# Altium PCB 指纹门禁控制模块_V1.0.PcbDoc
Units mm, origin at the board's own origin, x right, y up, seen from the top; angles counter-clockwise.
Board outline 60 x 20 mm, 2 copper layers (Top Layer, Bottom Layer); 45 components, 31 nets, 157 pads, 95 vias.
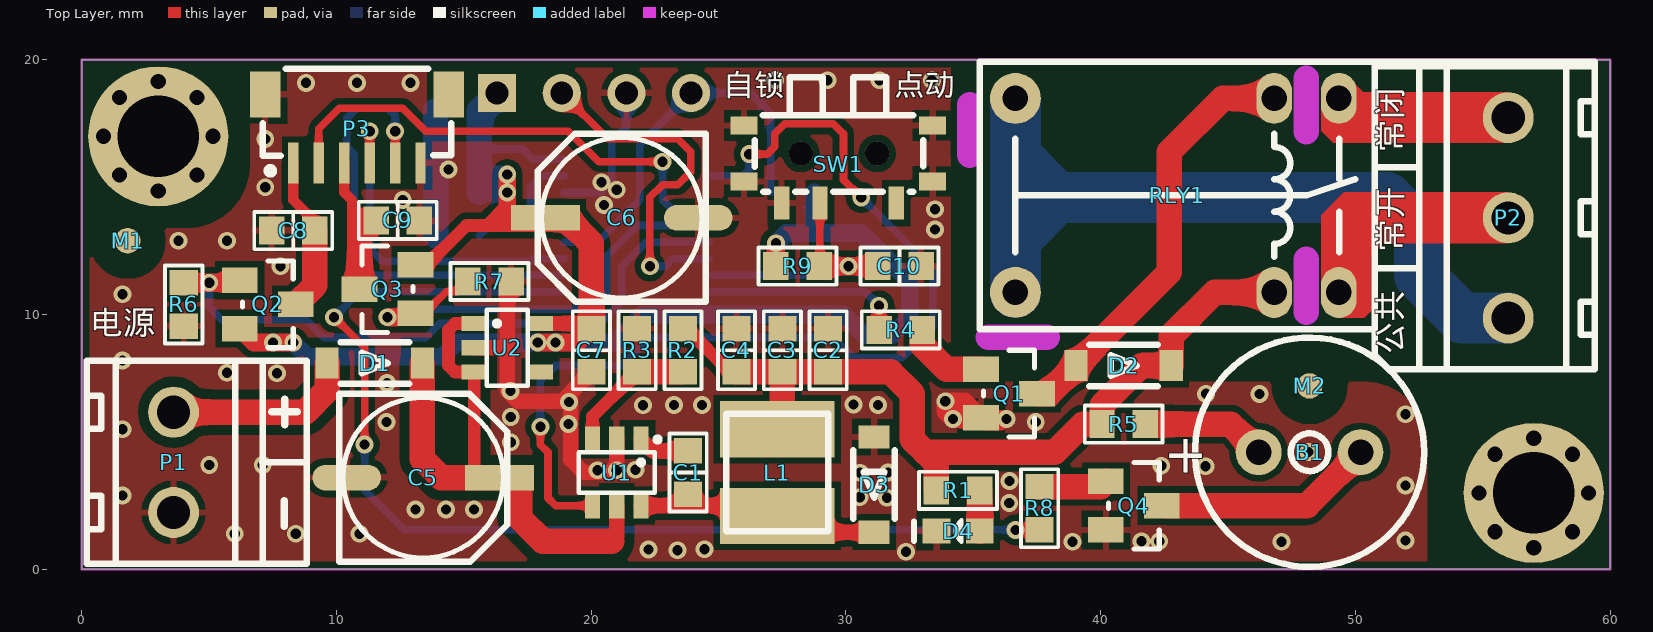
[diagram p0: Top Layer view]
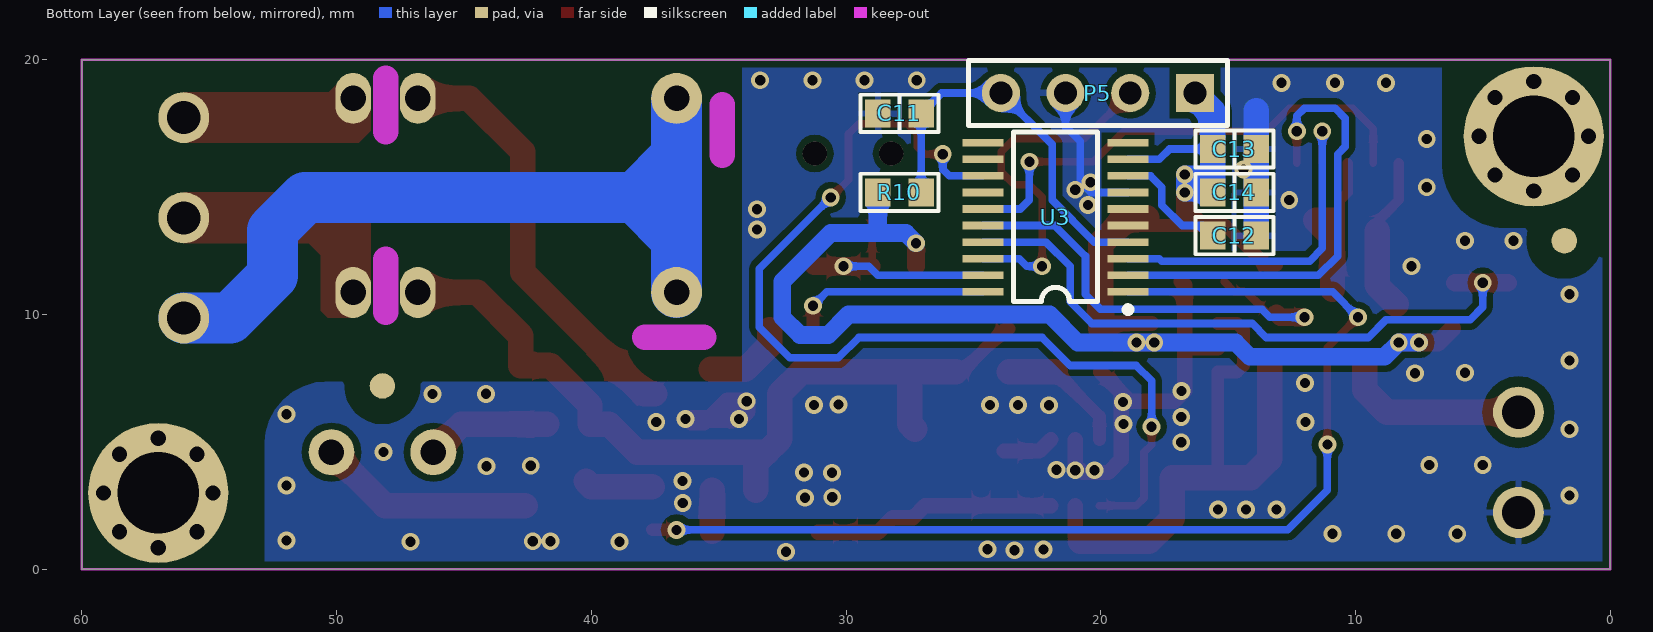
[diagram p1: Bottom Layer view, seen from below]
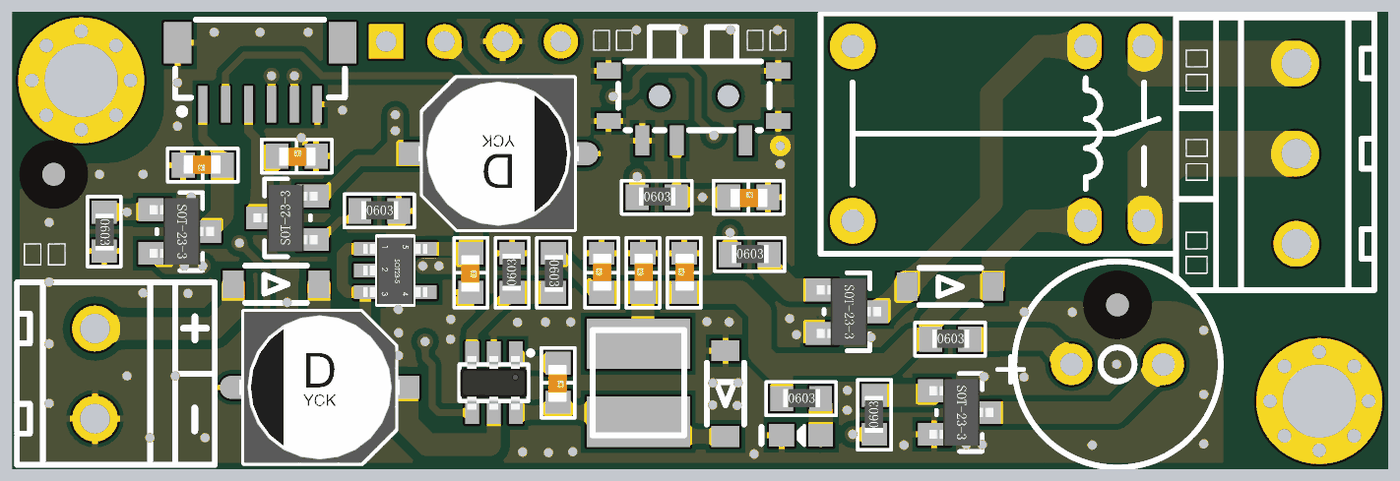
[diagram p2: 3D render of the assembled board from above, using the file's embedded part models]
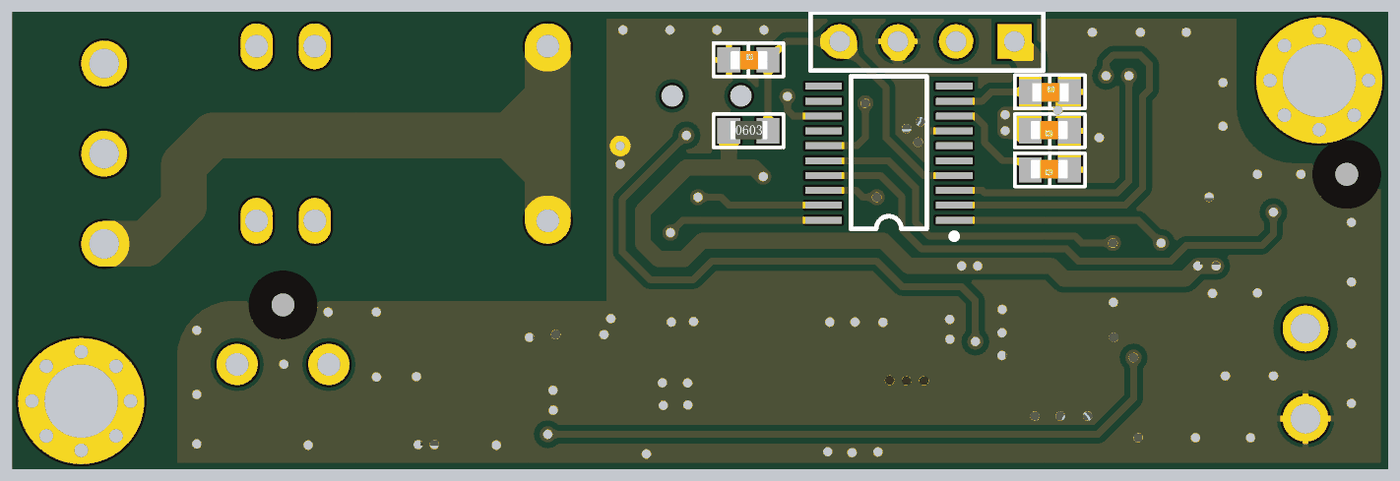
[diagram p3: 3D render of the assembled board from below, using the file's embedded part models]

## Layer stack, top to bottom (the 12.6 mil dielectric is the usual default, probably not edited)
Top Solder: solder mask 0.0102, Solder Resist, Dk 3.5
Top Layer: signal copper 0.0356
Dielectric 1: dielectric 0.32, FR-4, Dk 4.8
Bottom Layer: signal copper 0.0356
Bottom Solder: solder mask 0.0102, Solder Resist, Dk 3.5

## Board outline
0,0 60,0 60,20 0,20

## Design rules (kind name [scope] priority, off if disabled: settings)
Clearance Clearance_1 [InNet('NetD1_1') Or InNet('VIN') vs InPolygon] p1: gap=0.4
Clearance [All] p2: gap=0.254
ComponentClearance [All] p1: gap=0 collisioncheckmode=3 verticalgap=0 showdistances=FALSE
HoleSize [All] p1 off: absolutevalues=TRUE maxlimit=2.54 minlimit=0.025 maxpercent=80.000 minpercent=20.000
HoleToHoleClearance [All] p1 off: gap=0.254 allowstackedmicrovias=TRUE
LayerPairs [All] p1 off: enforce=TRUE
MinimumSolderMaskSliver [All] p1 off: minsoldermaskwidth=0.254
NetAntennae [All] p1 off: netantennaetolerance=0
PolygonConnect PolygonConnect_1 [InNet('GND') And isvia] p1: connectstyle=Direct reliefconductorwidth=0.254 reliefentries=4 polygonreliefangle="90 Angle" airgapwidth=0.254
PolygonConnect [All] p2: connectstyle=Relief reliefconductorwidth=0.254 reliefentries=4 polygonreliefangle="90 Angle" airgapwidth=0.254
RoutingVias [All] p1: holewidth=0.711 width=1.27 viastyle="Through Hole" minholewidth=0.1 minwidth=0.1 maxholewidth=0.711 maxwidth=1.27
SilkToBoardRegionClearance [All] p1 off:
SilkToSilkClearance [All] p1 off: silktosilkclearance=0.254
SilkToSolderMaskClearance [IsPad] p1 off: minsilkscreentomaskgap=0.254 clearancetoexposedcopper=TRUE
SolderMaskExpansion [All] p1: expansion=0.102
Width [All] p1: maxlimit=8 minlimit=0.254 preferedwidth=0.254
21 further rules are at their usual default settings.

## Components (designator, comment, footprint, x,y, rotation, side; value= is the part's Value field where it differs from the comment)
B1 "QMB-09B-03" BUZZER-9MM 48.2,4.6 r0 top
C1 "103 50V 10% X7R 0603" C0603 23.8,3.8 r270 top
C2 "10uF 10V 20% X5R 0603" C0603 29.3,8.6 r90 top
C3 "10uF 10V 20% X5R 0603" C0603 27.5,8.6 r90 top
C4 "104 16V 10% X7R 0603" C0603 25.7,8.6 r90 top
C5 "100uF 35V 贴片电解电容" CAP-D6.3XH7.7 13.4,3.6 r0 top
C6 "220uF 6.3V 贴片电解电容" CAP-D6.3XH7.7 21.2,13.8 r180 top
C7 "104 16V 10% X7R 0603" C0603 20,8.6 r270 top
C8 "104 16V 10% X7R 0603" C0603 8.3,13.3 r180 top
C9 "104 16V 10% X7R 0603" C0603 12.4,13.7 r0 top
C10 "104 16V 10% X7R 0603" C0603 32.1,11.9 r0 top
C11 "104 16V 10% X7R 0603" C0603 27.9,17.9 r180 bottom
C12 "1uF 10V 20% X5R 0603" C0603 14.75,13.1 r0 bottom
C13 "10uF 10V 20% X5R 0603" C0603 14.75,16.5 r180 bottom
C14 "104 16V 10% X7R 0603" C0603 14.75,14.8 r0 bottom
D1 "DSK34" SOD-123 11.5,8.1 r0 top
D2 "DSK34" SOD-123 40.9,8 r0 top
D3 "DSK34" SOD-123 31.1,3.325 r270 top
D4 "黄绿色 贴片LED" LED-0603 34.4,1.5 r180 top
L1 "4.7uH" L-SMD-4.5X4.0 27.3,3.8 r90 top
M1 "MARK" MARK 1.8,12.9 r0 top
M2 "MARK" MARK 48.2,7.2 r0 top
P1 "KF396-2 接线端子" KF396-2 3.6,4.2 r270 top
P2 "KF396-3 接线端子" KF396-3 56,13.8 r90 top
P3 "6P-1.0mm-立式贴片插座" "SH 1.0_LS_6P" 10.8,17.3 r0 top
P5 "STM8 烧写口" HDR1X4 16.3,18.7 r0 bottom
Q1 "S8050" SOT-23 36.4,6.9 r270 top
Q2 "SI2301" SOT-23 7.3,10.4 r270 top
Q3 "SI2301" SOT-23 12,11 r90 top
Q4 "S8050" SOT-23 41.3,2.5 r270 top
R1 "1K 1% 0603" R0603 34.4,3.1 r0 top
R2 "75K 1% 0603" R0603 23.6,8.6 r270 top
R3 "24K 1% 0603" R0603 21.8,8.6 r90 top
R4 "1K 1% 0603" R0603 32.15,9.4 r0 top
R5 "100R 1% 0603" R0603 40.9,5.7 r0 top
R6 "10K 1% 0603" R0603 4,10.4 r270 top
R7 "10K 1% 0603" R0603 16,11.3 r0 top
R8 "1K 1% 0603" R0603 37.6,2.4 r90 top
R9 "10K 1% 0603" R0603 28.1,11.9 r0 top
R10 "10K 1% 0603" R0603 27.9,14.8 r180 bottom
RLY1 "HK4100F-DC3V-SHG" RELAY-TH_HK4100F-XXX-XXXX 43,14.68 r180 top
SW1 "MSK12CO2-BDM" SW-SMD_MSK12CO2-BDM 29.7,15.9 r180 top
U1 "EUP3458VIR1" SOT-23-6 21,3.8 r180 top
U2 "HT7533" SOT-23-5 16.7,8.7 r270 top
U3 "STM8S003F3P6" TSSOP-20 21.7,14 r90 bottom

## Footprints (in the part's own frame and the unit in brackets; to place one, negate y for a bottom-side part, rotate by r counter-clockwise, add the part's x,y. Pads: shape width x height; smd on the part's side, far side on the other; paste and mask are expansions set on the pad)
BUZZER-9MM [mm]
  round 1.8 hole 1: 1(-2,0) 2(2,0)
  silkscreen extent -4.5,-4.5 4.5,4.5
C0603 [mm]
  rect 1x1.1 smd: 1(-0.85,0) 2(0.85,0)
  silkscreen extent -1.53,-0.73 1.53,0.73, body extent -0.78,-0.42 0.82,0.38, height 0.3
CAP-D6.3XH7.7 [mm] "贴片电解电容，直径6.3mm，高7.7mm"
  rect 2.7x1 smd: 1(3,0)
  oval 2.7x1 smd: 2(-3,0)
  silkscreen extent -3.3,-3.3 3.3,3.3, body extent -3.5,-3.3 3.5,3.3, height 7.7
HDR1X4 [mm] "Connector; Header; 4 Position"
  rect 1.5x1.5 hole 0.9: 1(0,0)
  round 1.5 hole 0.9: 2(2.54,0) 3(5.08,0) 4(7.62,0)
  silkscreen extent -1.27,-1.27 8.89,1.27
KF396-2 [mm]
  round 2 hole 1.3: 1(-1.968,0) 2(1.968,0)
  silkscreen extent -3.98,-3.4 3.98,3.5
KF396-3 [mm]
  round 2 hole 1.3: 1(-3.937,0) 2(0,0) 3(3.937,0)
  silkscreen extent -5.95,-3.4 5.95,3.5
L-SMD-4.5X4.0 [mm]
  rect 2.2x4.5 smd: 1(-1.7,0) 2(1.7,0)
  silkscreen extent -2.3,-2 2.3,2
LED-0603 [mil]
  rect 43x39 smd: 1(-33.5,0) 2(33.5,0)
  silkscreen extent -6,-17 68,17
MARK [mm] "MARK点，外径3mm，内径1mm"
  round 1 smd: 1(0,0)
  round 1 smd far side: 1(0,0)
  Top Layer pour cut-out: 0,1.5 0.074,1.5 0.294,1.478 0.577,1.393 0.837,1.253 1.066,1.066 1.253,0.837 1.393,0.577 1.478,0.294 1.5,0.074 1.5,0 1.5,0 1.5,0 1.5,-0.074 1.478,-0.294 1.393,-0.577 1.253,-0.837 1.066,-1.066 0.837,-1.253 0.577,-1.393 0.294,-1.478 0.074,-1.5 0,-1.5 0,-1.5 -0.074,-1.5 -0.294,-1.478 -0.577,-1.393 -0.837,-1.253 -1.066,-1.066 -1.253,-0.837 -1.393,-0.577 -1.478,-0.294 -1.5,-0.074 -1.5,0 -1.5,0 -1.5,0 -1.5,0.074 -1.478,0.294 -1.393,0.577 -1.253,0.837 -1.066,1.066 -0.837,1.253 -0.577,1.393 -0.294,1.478 -0.074,1.5 0,1.5
  Bottom Layer pour cut-out: 0,1.5 -0.074,1.5 -0.294,1.478 -0.577,1.393 -0.837,1.253 -1.066,1.066 -1.253,0.837 -1.393,0.577 -1.478,0.294 -1.5,0.074 -1.5,0 -1.5,0 -1.5,0 -1.5,-0.074 -1.478,-0.294 -1.393,-0.577 -1.253,-0.837 -1.066,-1.066 -0.837,-1.253 -0.577,-1.393 -0.294,-1.478 -0.074,-1.5 0,-1.5 0,-1.5 0.074,-1.5 0.294,-1.478 0.577,-1.393 0.837,-1.253 1.066,-1.066 1.253,-0.837 1.393,-0.577 1.478,-0.294 1.5,-0.074 1.5,0 1.5,0 1.5,0 1.5,0.074 1.478,0.294 1.393,0.577 1.253,0.837 1.066,1.066 0.837,1.253 0.577,1.393 0.294,1.478 0.074,1.5 0,1.5
R0603 [mm]
  rect 1x1.1 smd: 1(-0.85,0) 2(0.85,0)
  silkscreen extent -1.53,-0.73 1.53,0.73, body extent -0.78,-0.37 0.83,0.43, height 0.45
RELAY-TH_HK4100F-XXX-XXXX [mm]
  oval 1.4x2 hole 1: 1(-6.35,3.81) 2(-6.35,-3.81) 3(-3.81,3.81) 4(-3.81,-3.81)
  round 2 hole 1: 5(6.35,3.81) 6(6.35,-3.81)
  silkscreen extent -7.75,-5.25 7.75,5.25
"SH 1.0_LS_6P" [mm] "立式，1mm间距插座"
  rect 1.2x1.8 smd: 0(-3.6,1.345) 0(3.6,1.345)
  rect 0.4x1.6 smd: 1(-2.5,-1.345) 2(-1.5,-1.345) 3(-0.5,-1.345) 4(0.5,-1.345) 5(1.5,-1.345) 6(2.5,-1.345)
  silkscreen extent -3.7,-1.8 3.7,2.35
SOD-123 [mm]
  rect 0.909x1.219 smd: 1(-1.87,0) 2(1.87,0)
  silkscreen extent -1.35,-0.81 1.35,0.81
SOT-23 [mm]
  rect 1x1.4 smd: 1(-0.95,-1.1) 2(0.95,-1.1) 3(0,1.1)
  silkscreen extent -1.7,-1 1.7,1, body extent -1.45,-1.31 1.45,1.49, height 1.2
SOT-23-5 [mm]
  rect 0.6x1 smd: 1(-0.95,-1.3) 2(0,-1.3) 3(0.95,-1.3) 4(0.95,1.3) 5(-0.95,1.3)
  silkscreen extent -1.5,-0.8 1.5,0.8, body extent -1.45,-1.4 1.45,1.4, height 1.09
SOT-23-6 [mm]
  rect 0.6x1 smd: 1(-0.95,-1.3) 2(0,-1.3) 3(0.95,-1.3) 4(0.95,1.3) 5(0,1.3) 6(-0.95,1.3)
  silkscreen extent -1.7,-1.4 1.5,0.8, body extent -1.45,-1.17 1.47,1.17, height 1
SW-SMD_MSK12CO2-BDM [mm]
  rect 0.6x1.3 smd: 1(2.225,1.525) 2(0.725,1.525) 3(-2.275,1.525)
  rect 1.05x0.7 smd: 4(-3.7,-1.525) 4(-3.7,0.675) 4(3.7,0.675) 4(3.7,-1.525)
  round 0.95 hole 0.95 unplated: ""(-1.525,-0.425) ""(1.475,-0.425)
  silkscreen extent -3.33,-3.42 3.27,1.08
TSSOP-20 [mm]
  rect 0.3x1.6 smd: 1(-3.103,-2.774) 2(-2.453,-2.774) 3(-1.803,-2.774) 4(-1.153,-2.774) 5(-0.503,-2.774) 6(0.147,-2.774) 7(0.797,-2.774) 8(1.447,-2.774) 9(2.097,-2.774) 10(2.747,-2.774) 11(2.747,2.926) 12(2.097,2.926) 13(1.447,2.926) 14(0.797,2.926) 15(0.147,2.926) 16(-0.503,2.926) 17(-1.153,2.926) 18(-1.803,2.926) 19(-2.453,2.926) 20(-3.103,2.926)
  silkscreen extent -3.93,-2.9 3.17,1.73

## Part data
C1 C2 C3 C4 C7 C8 C9 C10 C11 C12 C13 C14: library part CapN, "CAP"
C5 C6: library part CapH, "100uF,35V,插件电解电容"
D1 D2 D3: library part 1N4007
D4: library part LED, "LED"
L1: library part InductorDM, "MSCD43-4R7MT"
P1: library part "Header 2", "Header, 2-Pin"
P2: library part "Header 3", "Header, 3-Pin"
P3: library part "Header 6", "Header, 6-Pin"
P5: library part "Header 4", "Header, 4-Pin"
Q1 Q4: library part NPN, "NPN晶体管"
Q2 Q3: library part MOSFET-P
R1 R2 R3 R4 R5 R6 R7 R8 R9 R10: library part Res1, "Resistor"
U2: library part HT7533_C105222
U3: "STM8S003F3P6,意法8位单片机"

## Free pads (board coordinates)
  round 0.7 hole 0.6: 0(0.85,17) 0(1.48,15.48) 0(1.48,18.52) 0(3,14.85) 0(3,19.15) 0(4.52,15.48) 0(4.52,18.52) 0(5.15,17) 0(54.85,3) 0(55.48,1.48) 0(55.48,4.52) 0(57,0.85) 0(57,5.15) 0(58.52,1.48) 0(58.52,4.52) 0(59.15,3)
  round 5.5 hole 3.2: 0(3,17) 0(57,3)

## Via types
v1: diameter 0.7, hole 0.4, Top Layer to Bottom Layer, tented both sides, 94 vias
v2: diameter 0.7, hole 0.4, Top Layer to Bottom Layer, 1 vias

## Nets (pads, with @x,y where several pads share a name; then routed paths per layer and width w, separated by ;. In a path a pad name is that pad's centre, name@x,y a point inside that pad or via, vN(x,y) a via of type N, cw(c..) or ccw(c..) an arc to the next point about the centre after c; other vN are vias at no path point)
3V3: C2.1 C3.1 C4.1 D2.2 L1.2 R1.1 R2.1 R5.1 RLY1.3 | length 34
  Top Layer w0.5: R2.1 23.75,9.45 25.45,7.75 C4.1
  Top Layer w1: C4.1 C3.1 ; L1.2 27.5,5.7 C3.1 ; R1.1 33.55,4.15 33.1,4.6 ; RLY1.3 44.47,10.87 42.77,9.17 D2.2 41.6,8 40.05,6.45 R5.1 39.3,5.7 38.2,4.6 33.1,4.6 ; C3.1 C2.1 31.75,7.75 32.6,6.9 32.6,5.1 33.1,4.6
BEEP: R8.1 U3.1 | length 43.9
  Top Layer w0.3: v1(9.9,9.9) 11.1,8.7 v1(11.1,4.9)
  Top Layer w0.5: v1(36.65,1.55) R8.1
  Bottom Layer w0.3: v1(9.9,9.9) 10.897,10.897 U3.1 ; v1(11.1,4.9) 11.1,3.1 12.65,1.55 v1(36.65,1.55)
F_INT: P3.2 U3.15 | length 19.5
  Top Layer w0.3: P3.2 9.3,17.3 10.1,18.1 12.6,18.1 13.5,17.2 19.1,17.2 20.3,16 v1(22.8,16)
  Bottom Layer w0.3: v1(22.8,16) 22.8,14.5 23.153,14.147 U3.15
F_RXD: P3.5 U3.2 | length 18.1
  Top Layer w0.3: P3.5 v1(12.3,17.2)
  Bottom Layer w0.3: v1(12.3,17.2) 12.3,17.8 12,18.1 10.8,18.1 10.4,17.7 10.4,16.6 10.7,16.3 10.7,12.3 11.453,11.547 U3.2
F_TXD: P3.4 U3.3 | length 13.7
  Top Layer w0.3: P3.4 v1(11.3,17.2)
  Bottom Layer w0.3: v1(11.3,17.2) 11.3,12.6 11.799,12.101 17.601,12.101 17.697,12.197 U3.3
FM_3V3: C9.1 P3.3 Q3.3 | length 6.2
  Top Layer w0.4: P3.3 10.3,14.8 10.6,14.5 10.6,12.8
  Top Layer w1: Q3.3 10.9,13.05 C9.1
FM_EN: Q3.1 R7.1 U3.16 | length 18.7
  Top Layer w0.3: Q3.1 13.45,10.05 14.3,10.9 14.75,10.9 R7.1
  Top Layer w0.7: v1(12,9.9) 12.95,9.9 Q3.1
  Bottom Layer w0.3: v1(12,9.9) 13.363,9.9 13.671,10.208 20.008,10.208 20.6,10.8 20.6,12.3 21.797,13.497 U3.16
FT_3V3: C8.1 P3.1 Q2.3 | length 6.2
  Top Layer w0.4: P3.1 8.3,14.5 9.15,13.65 C8.1
  Top Layer w1: Q2.3 9.15,11.15 C8.1
FT_EN: Q2.1 R6.1 U3.17 | length 25.5
  Top Layer w0.7: R6.1 v1(5,11.25) Q2.1@6.1,11.25
  Bottom Layer w0.3: v1(5,11.25) 5,10.3 5.5,9.8 8.8,9.8 9.5,9.1 13.5,9.1 14.054,9.654 20.354,9.654 21.2,10.5 21.2,11.9 22.147,12.847 U3.17
GND: C2.2 C3.2 C4.2 C5.2 C6.2 C7.2 C8.2 C9.2 C10.2 C11.1 C12.1 C13.2 C14.1 D3.1 D4.2 P1.2 P3.0@7.2,18.645 P3.6 P5.3 Q1.2 Q4.2 R3.2 R6.2 R7.2 SW1.1 SW1.4 U1.2 U2.2 U3.7 | length 32.9
  Top Layer w0.5: v1@34.2,5.95 Q1.2 35.35,5.9 35.55,5.7 36.1,5.7 v1(36.3,5.9)
  Top Layer w0.6: U2.2 16.7,8.7 ; R7.2 16.7,11.15 16.7,8.7 ; C7.2 19.196,6.946 ; U1.2 21,4.1 20.7,3.8 19.7,3.8 19.196,4.304 19.196,6.946 ; 16.7,8.7 16.7,7 17.1,6.6 18.85,6.6 19.196,6.946
  Top Layer w0.7: Q1.2 34.65,6.6 v1(33.9,6.6) 33.9,6.2 v1(34.2,5.9) 35.35,5.9 v1(36.3,5.9)
  Bottom Layer w0.3: U3.7 20.397,14.797 20.8,15.2 20.8,16.8 21.38,17.38 P5.3
  Bottom Layer w1: C12.1 C14.1 C13.2 13.9,18
  other v1: 32.35,0.69 23.38,0.75 22.25,0.78 24.44,0.79 38.89,1.08 47.1,1.08 41.6,1.1 42.3,1.1 51.96,1.13 6,1.4 8.4,1.4 10.9,1.4 13.1,2.35 14.3,2.35 15.4,2.35 36.41,2.6 31.61,2.81 30.54,2.83 1.6,2.9 51.96,3.29 36.42,3.47 30.55,3.79 31.65,3.8 20.24,3.89 21,3.89 21.74,3.91 44.12,4.05 42.38,4.07 5,4.1 7.1,4.1 48.16,4.61 16.84,4.99 1.6,5.5 19.11,5.7 11.96,5.79 37.45,5.78 16.84,5.98 51.96,6.09 22.03,6.44 23.25,6.45 24.35,6.45 31.26,6.45 30.29,6.47 19.12,6.57 46.23,6.88 44.13,6.89 16.83,7 11.98,7.31 5.7,7.72 7.66,7.7 1.6,8.2 1.6,10.8 7.8,11.9 3.8,12.9 5.7,12.9 33.49,13.34 20.5,14.3 12.6,14.5 21,14.9 7.2,15 20.4,15.2 14.4,15.7 7.2,16.9 8.8,19.1 10.8,19.1 12.9,19.1 27.22,19.2 29.27,19.2 31.32,19.2 33.37,19.2
  other v2: 33.49,14.14
M_3V3: C6.1 C7.1 C13.1 C14.2 P5.1 Q2.2 Q3.2 R9.1 R10.1 U2.5 U3.9 | length 69.6
  Top Layer w0.5: Q3.2 13.55,11.95 15.1,13.5 15.9,13.5 ; 16.7,14.3 15.9,13.5 ; 19.6,13.5 15.9,13.5
  Top Layer w0.6: U2.5 19.8,9.65 C7.1
  Top Layer w0.7: Q2.2 6.75,8.9 v1(7.5,8.9) v1(8.3,8.9) ; 16.7,13.8 16.7,14.3 v1(16.7,14.8) v1(16.7,15.5) ; v1(17.9,8.9) v1(18.6,8.9) 19.45,8.9 C7.1 ; R9.1 v1(27.25,12.8)
  Top Layer w1: C6.1 19,13.8 20,12.8 C7.1
  Bottom Layer w0.3: C13.1@15.703,16.097 15.6,16.2 15.9,16.5 17.3,16.5 17.703,16.097 U3.9
  Bottom Layer w0.7: v1(7.5,8.9) v1(8.3,8.9) 8.854,8.346 14.146,8.346 14.7,8.9 v1(17.9,8.9) v1(18.6,8.9) 20.9,8.9 22,10 29.9,10 30.7,9.2 31.8,9.2 32.5,9.9 32.5,11.3 30.6,13.2 28.9,13.2 ; 15.75,15.5 v1(16.7,15.5) v1(16.7,14.8) C14.2@15.9,14.8 ; v1(27.25,12.8) 27.65,13.2 28.6,13.2 ; R10.1 28.75,13.35 ; 28.6,13.2 28.9,13.2 ; 28.6,13.2 28.75,13.35 ; 28.75,13.35 28.9,13.2
  Bottom Layer w1: C14.2 15.6,16.2 C13.1 15.6,18 P5.1
NetB1_1: B1.1 R5.2 | length 4.9
  Top Layer w1: R5.2 45.1,5.7 B1.1
NetB1_2: B1.2 Q4.3 | length 8.5
  Top Layer w1: Q4.3@42.6,2.5 48.1,2.5 B1.2
NetC1_1: C1.1 U1.1 | length 2
  Top Layer w0.6: U1.1 22.4,4.65 C1.1
NetC1_2: C1.2 D3.2 L1.1 U1.6 | length 9.6
  Top Layer w0.6: U1.6 26.9,2.5 L1.1 27.37,2.03 28.17,2.03 28.745,1.455 D3.2
NetC12_2: C12.2 U3.8 | length 4.7
  Bottom Layer w0.3: C12.2 16,13.5 16.8,13.5 17.6,14.3 17.6,15 18.047,15.447 U3.8
NetD1_1: D1.1 P1.1 | length 7.5
  Top Layer w1: P1.1 8.769,6.168 9.63,7.03 D1.1
NetD2_1: D2.1 Q1.3 RLY1.4 | length 16.9
  Top Layer w1: Q1.3 37.93,6.9 D2.1 42.7,11.67 42.7,16.4 44.79,18.49 RLY1.4
NetD4_1: D4.1 R1.2 | length 1.6
  Top Layer w1: D4.1@35.25,1.501 R1.2
NetQ1_1: Q1.1 R4.2 | length 3.3
  Top Layer w1: R4.2 33,8.8 33.95,7.85 Q1.1
NetQ4_1: Q4.1 R8.2 | length 2.7
  Top Layer w1: R8.2 40,3.25 Q4.1
NetR2_2: R2.2 R3.1 U1.3 | length 5.2
  Top Layer w0.5: U1.3 20.05,6 R3.1
  Top Layer w1: R3.1 R2.2
NRST: C11.2 P5.4 R10.2 U3.4 | length 15.3
  Bottom Layer w0.3: U3.4 20.247,12.847 21.9,14.5 21.9,16.68 P5.4 26.25,18.7 C11.2 R10.2
PWR_EN: U1.4 U3.13 | length 39.5
  Top Layer w0.3: v1(18,5.6) 18,4.9 18.3,4.6 18.3,2.8 18.6,2.5 U1.4 ; v1(26.2,16.3) 26.9,16.3 27.2,16.6 27.2,17.1 27.6,17.5 29.5,17.5 29.9,17.1 29.9,15.3 v1(30.6,14.6)
  Bottom Layer w0.3: v1(18,5.6) 18,7.4 18.6,8 21.2,8 22.3,9.1 29.5,9.1 30.3,8.3 32.2,8.3 33.4,9.5 33.4,11.8 v1(30.6,14.6) ; U3.13 25.947,15.447 26.2,15.7 v1(26.2,16.3)
RLY_1: R4.1 U3.20 | length 7.9
  Top Layer w0.5: R4.1 v1(31.3,10.35)
  Bottom Layer w0.3: U3.20 30.753,10.897 v1(31.3,10.35)
RLY_CLOSE: P2.3 RLY1.2 | length 7
  Top Layer w1: RLY1.2 50.103,17.737 P2.3
RLY_COM: P2.1 RLY1.5 RLY1.6 | length 34.5
  Bottom Layer w2: RLY1.5 36.65,14.6 ; 36.65,12.96 38.29,14.6 ; RLY1.6@36.65,18.41 36.65,16.24 ; P2.1 54.187,9.863 52.52,11.53 52.52,13.31 51.23,14.6 38.29,14.6 ; 36.65,14.6 38.29,14.6 ; 36.65,14.6 36.65,16.24 ; 36.65,16.24 38.29,14.6
RLY_OPEN: P2.2 RLY1.1 | length 9.1
  Top Layer w1: RLY1.1 49.35,13.05 50.1,13.8 P2.2
SW_MODE: C10.1 R9.2 SW1.2 U3.19 | length 10.2
  Top Layer w0.3: R9.2@28.975,11.925 R9.2@29,11.9 ; R9.2@28.975,12.125 SW1.2
  Top Layer w0.7: R9.2@29,11.9 C10.1
  Bottom Layer w0.3: U3.19 28.747,11.547 29.1,11.9 v1(30.1,11.9)
SWIM: P5.2 U3.18 | length 14
  Top Layer w0.3: P5.2 20.64,16.9 23.4,16.9 23.9,16.4 23.9,15.6 23.4,15.1 22.8,15.1 22.3,14.6 v1(22.3,11.9)
  Bottom Layer w0.3: v1(22.3,11.9) 22.9,11.9 23.197,12.197 U3.18
VIN: C5.1 D1.2 U1.5 U2.1 U2.3 | length 22.7
  Top Layer w0.5: C5.1@15.4,3.6 U2.3 14.65,7.75 14.396,8.004 14.396,9.396 14.65,9.65 U2.1
  Top Layer w0.6: 20.8,1.1 21,1.3 U1.5
  Top Layer w1: D1.2 13.37,4.33 14.1,3.6 17.2,3.6 17.2,2 18.1,1.1 20.8,1.1
pads on no net: M1.1 M2.1 P3.0@14.4,18.645 SW1. SW1.3 U2.4 U3.5 U3.6 U3.10 U3.11 U3.12 U3.14

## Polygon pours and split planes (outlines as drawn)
GND on Top Layer "GND" (solid, remove dead copper, pour order 0): 0,0 0,20 60,20 60,0
GND on Bottom Layer "GND" (solid, remove dead copper, pour order 2): 0,0 0,20 60,20 60,0

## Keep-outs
Keep-Out Layer:
  lines w0.1: 0,0 60,0 60,20 0,20 0,0
  lines w1: 34.85,16.25 34.85,18.25 ; 35.59,9.11 37.9,9.11 ; 48.07,10.09 48.07,12.18 ; 48.07,17.18 48.07,19.29

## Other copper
Top Layer:
  rectangle net FM_3V3: 10.6,13.4 11.5,14.2
  pour cut-out: 0,19.99 6.61,19.99 6.61,15.93 cw(c4.07,15.93) 4.07,13.39 0,13.39
  pour cut-out: 60,20 34.11,20 34.11,7.37 50.34,7.37 cw(c50.34,4.89) 52.82,4.89 52.82,0 60,0
  region net RLY_CLOSE: 49.35,18.41 48.65,18.41 48.65,17.21 49.12,16.74 56,16.74 56,18.73 50.31,18.73 49.81,19.23 49.35,18.77
  region net RLY_OPEN: 49.35,10.79 48.65,10.79 48.65,13.91 49.54,14.8 56,14.8 56,12.81 51.09,12.81 50.62,12.34 50.62,10.15 50.34,9.87 49.35,9.87
Bottom Layer:
  pour cut-out: 0,19.99 6.61,19.99 6.61,15.93 cw(c4.07,15.93) 4.07,13.39 0,13.39
  pour cut-out: 60,20.002 34.08,20.002 34.08,7.372 50.34,7.372 cw(c50.34,4.892) 52.82,4.892 52.82,0.002 60,0.002

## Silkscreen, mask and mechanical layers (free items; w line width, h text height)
Top Overlay:
  lines w0.254: 7.09,4.2 8.82,4.2 ; 7.1,0.219 8.83,0.219 8.83,8.182 7.1,8.182 ; 27.789,17.825 27.789,19.325 29.089,19.325 29.089,17.825 ; 50.75,11.817 52.5,11.817 ; 50.75,15.783 52.5,15.783 ; 50.75,19.93 59.4,19.93 59.4,19.75 ; 52.5,7.85 51.32,7.85 50.75,8.42 50.75,19.75 52.5,19.75
  lines w0.3: 7.46,6.18 8.46,6.18 ; 7.95,1.699 7.95,2.699 ; 7.96,5.68 7.96,6.68
  text "自锁" at 25.2,18.3 h1.5
  text "点动" at 31.9,18.3 h1.5
  text "常闭" at 52.14,16.37 h1.6 r90
  text "常开" at 52.14,12.47 h1.6 r90
  text "电源" at 0.35,8.92 h1.6
  text "公共" at 52.136,8.42 h1.6 r90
